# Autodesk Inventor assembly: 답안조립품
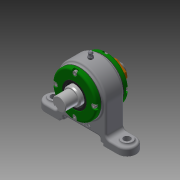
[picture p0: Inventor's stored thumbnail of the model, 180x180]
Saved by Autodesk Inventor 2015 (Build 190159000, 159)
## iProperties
Created: 2019-05
Part Number: 답안조립품
Document SubType Name: Assembly
Designer: now
Author: now
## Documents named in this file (13)
- C:\Users\now\Desktop\490504V1040\답안조립품.iam
- C:\Users\now\Desktop\490504V1040\개스킷.ipt
- C:\Users\now\Desktop\490504V1040\그리스니플 M6.ipt
- 그리스니플  M6.ipt
- C:\Users\now\Desktop\490504V1040\그리스니플개스킷.ipt
- C:\Users\now\Desktop\490504V1040\베어링너트.ipt
- C:\Users\now\Desktop\490504V1040\본체.ipt
- C:\Users\now\Desktop\490504V1040\볼트 M4.ipt
- C:\Users\now\Desktop\490504V1040\앵귤러 볼 베어링 7205.ipt
- C:\Users\now\Desktop\490504V1040\오일 실 28 40 5 B.ipt
- C:\Users\now\Desktop\490504V1040\축.ipt
- C:\Users\now\Desktop\490504V1040\칼라.ipt
- C:\Users\now\Desktop\490504V1040\커버.ipt
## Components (4 placed, 3 different names)
1. 개스킷:1
2. 그리스니플  M6:1
3. 그리스니플개스킷:1
4. 개스킷:2
